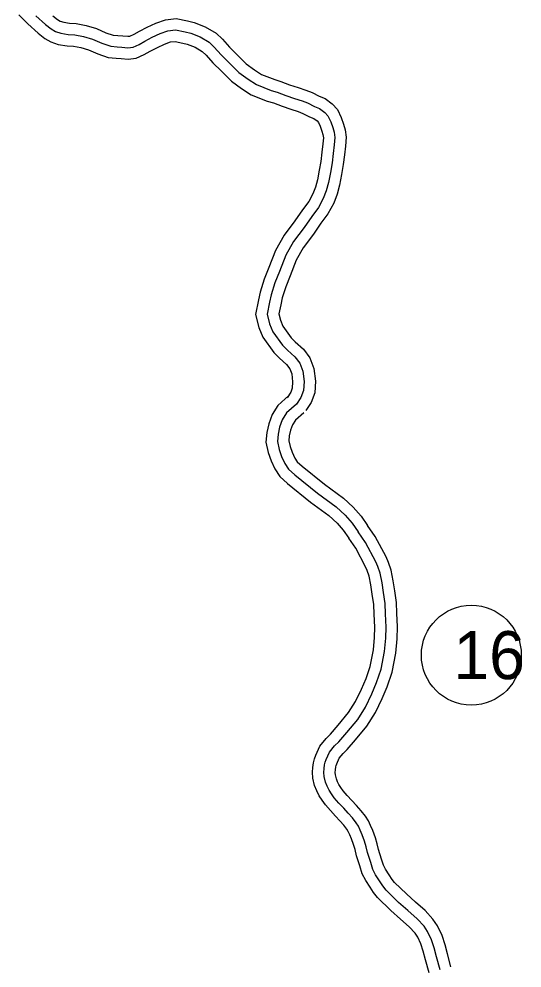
# Model space of a CAD drawing. Extents: x 31699 to 244310, y -8841 to 11474.
# Drawn here: x 96930 to 97373, y 7933 to 8769 of the extents above; entities that cross this region are included whole.
import ezdxf

# ---------------------------------------------------------------- set-up
doc = ezdxf.new("R2010")
doc.units = 0
for name, color, linetype in [('B_Logo', 7, 'Continuous'), ('R_Border Notes', 7, 'Continuous'), ('R_XS_EARTHWORK_STAGE2', 7, 'Continuous')]:
    doc.layers.add(name, color=color, linetype=linetype)

msp = doc.modelspace()

# ---------------------------------------------------------------- linework, layer by layer
at = {"layer": 'B_Logo'}
for points in [[(96945, 8771.56), (96953.67, 8763.78), (96958.51, 8759.97), (96962.46, 8757.74), (96967.2, 8756.06), (96973.67, 8754.93), (96979.47, 8754.67), (96987.13, 8753.35), (96995.15, 8750.84), (97003.31, 8747.26), (97011.06, 8744.68), (97016.66, 8744.08), (97020.99, 8743.86), (97026.19, 8743.39), (97030.77, 8743.97), (97036.14, 8746.37), (97041.16, 8749.1), (97047.71, 8752.64), (97054.53, 8755.86), (97061.43, 8758.27), (97068.14, 8759.02), (97076.68, 8757.31), (97081.55, 8756.17), (97089.71, 8752.86), (97097.75, 8748.14), (97102.26, 8743.86), (97108.33, 8736.99), (97115.6, 8729.8), (97123.94, 8721.68), (97132, 8715.7), (97139.37, 8710.92), (97152.21, 8705.86), (97157.55, 8704.18), (97165.31, 8701.27), (97172.92, 8698.82), (97179.6, 8696.56), (97184.42, 8694.75), (97190.44, 8691.68), (97194.79, 8689.79), (97199.49, 8686.38), (97202.32, 8683.27), (97204.84, 8678.23), (97206.56, 8673.05), (97207.8, 8668.99), (97208.32, 8664.26), (97207.93, 8657.78), (97206.95, 8650.16), (97205.98, 8641.88), (97204.54, 8633.65), (97202.84, 8624.69), (97200.79, 8617.39), (97198.27, 8610.62), (97193.9, 8602.63), (97188.07, 8594.76), (97181.39, 8584.94), (97172.07, 8572.82), (97165.29, 8560.67), (97159.66, 8546.19), (97155.71, 8536.27), (97152.43, 8525.69), (97150.97, 8519.26), (97148.7, 8508.69), (97150.99, 8500.25), (97153.86, 8493.27), (97162.31, 8481.49), (97166.69, 8477.2), (97173.28, 8471.21), (97177.54, 8465.51), (97180.21, 8458.61), (97181.31, 8449.48), (97180.8, 8441.66), (97178.6, 8435.5), (97174.61, 8429.51)], [(97174.61, 8429.51), (97165.98, 8421.87), (97162.12, 8415.82), (97159.79, 8409.39), (97158.4, 8403.04), (97157.87, 8396.69), (97159.28, 8389.57), (97161.48, 8383.52), (97164.35, 8377.28), (97167.53, 8372.24), (97173.25, 8367.24), (97193.13, 8351.25), (97209.64, 8339.16), (97217.51, 8331.78), (97223.71, 8324.84), (97229.05, 8317.03)], [(97301.02, 7931.31), (97297.87, 7942.88), (97295.84, 7950.73), (97293.55, 7957.91), (97290.13, 7965.21), (97286.94, 7969.84), (97280.93, 7976.36), (97272.79, 7983.6), (97264.57, 7990.83), (97253.52, 8001.63), (97250.68, 8005.27), (97247.82, 8009.7), (97244.22, 8015.13), (97241.9, 8019.77), (97240.03, 8025.88), (97237.12, 8034.59), (97235.85, 8039.71), (97234.52, 8044.7), (97232.45, 8050.35), (97230.74, 8054.33), (97229.1, 8057.85), (97227.19, 8060.96), (97223.94, 8065.12), (97220.23, 8069.34), (97216.18, 8073.63), (97211.93, 8078.24), (97207.87, 8082.93), (97205.37, 8086.37), (97203.33, 8089.54), (97201.62, 8092.99), (97200.17, 8096.71), (97198.98, 8101.64), (97198.73, 8105.3), (97199.09, 8108.58), (97199.44, 8111.92), (97200.01, 8114.26), (97200.85, 8116.61), (97203.76, 8122.99), (97208.21, 8128.52), (97211.82, 8132.18), (97218.84, 8140.35), (97228.6, 8151.96), (97235.45, 8162.73), (97240.89, 8174.35), (97245.22, 8184.28), (97249.26, 8196.02), (97252.25, 8211.68), (97253.3, 8223.44), (97253.5, 8233.25), (97253.08, 8244.93), (97252.63, 8254), (97251.24, 8263.6), (97250, 8272.19), (97248.23, 8280.71), (97246.35, 8286.63), (97244.5, 8290.81), (97235.36, 8307.84), (97229.05, 8317.03)]]:
    msp.add_lwpolyline(points, dxfattribs=at)
at = {"layer": 'R_Border Notes'}
msp.add_circle((97328.61, 8208.51), 44, dxfattribs=at)
at = {"layer": 'R_XS_EARTHWORK_STAGE2'}
for points in [[(96930.3, 8772.49), (96938.03, 8764.37), (96947.23, 8756.12), (96952.92, 8751.63), (96958.31, 8748.6), (96964.66, 8746.35), (96972.58, 8744.97), (96978.39, 8744.71), (96984.79, 8743.61), (96991.64, 8741.46), (96999.72, 8737.92), (97008.92, 8734.86), (97015.87, 8734.11), (97020.28, 8733.89), (97026.37, 8733.33), (97033.5, 8734.24), (97040.57, 8737.4), (97045.93, 8740.31), (97052.23, 8743.72), (97058.33, 8746.59), (97063.66, 8748.46), (97067.71, 8748.91), (97074.56, 8747.54), (97078.51, 8746.61), (97085.28, 8743.86), (97091.7, 8740.1), (97095.05, 8736.91), (97101.06, 8730.11), (97108.6, 8722.66), (97117.45, 8714.05), (97126.29, 8707.49), (97134.77, 8701.98), (97148.88, 8696.42), (97154.3, 8694.72), (97162.01, 8691.82), (97169.79, 8689.32), (97176.24, 8687.14), (97180.37, 8685.58), (97186.18, 8682.63), (97189.8, 8681.06), (97192.78, 8678.89), (97193.99, 8677.56), (97195.57, 8674.4), (97197.03, 8670), (97197.96, 8666.96), (97198.29, 8664.01), (97197.97, 8658.72), (97197.02, 8651.38), (97196.08, 8643.32), (97194.7, 8635.44), (97193.1, 8626.98), (97191.28, 8620.49), (97189.15, 8614.79), (97185.46, 8608.04), (97179.91, 8600.55), (97173.28, 8590.81), (97163.7, 8578.34), (97156.22, 8564.94), (97150.35, 8549.85), (97146.27, 8539.6), (97142.77, 8528.28), (97141.21, 8521.42), (97138.41, 8508.42), (97141.5, 8497.02), (97145.06, 8488.39), (97154.69, 8474.96), (97159.82, 8469.93), (97165.84, 8464.45), (97168.7, 8460.62), (97170.43, 8456.16), (97171.27, 8449.2), (97170.91, 8443.7), (97169.6, 8440.02), (97166.29, 8435.06)], [(96960.11, 8771.44), (96964.09, 8768.3), (96966.61, 8766.88), (96969.75, 8765.77), (96974.76, 8764.89), (96980.54, 8764.63), (96989.48, 8763.1), (96998.66, 8760.22), (97006.91, 8756.61), (97013.2, 8754.51), (97017.45, 8754.05), (97021.69, 8753.84), (97026, 8753.45), (97028.04, 8753.71), (97031.71, 8755.35), (97036.4, 8757.89), (97043.2, 8761.57), (97050.74, 8765.12), (97059.2, 8768.09), (97068.58, 8769.13), (97078.81, 8767.09), (97084.6, 8765.72), (97094.14, 8761.85), (97103.81, 8756.19), (97109.47, 8750.8), (97115.6, 8743.86), (97122.6, 8736.94), (97130.44, 8729.32), (97137.7, 8723.92), (97143.97, 8719.85), (97155.54, 8715.29), (97160.81, 8713.64), (97168.6, 8710.71), (97176.05, 8708.32), (97182.97, 8705.98), (97188.46, 8703.91), (97194.7, 8700.73), (97199.78, 8698.53), (97206.19, 8693.87), (97210.64, 8688.99), (97214.1, 8682.06), (97216.09, 8676.09), (97217.64, 8671.02), (97218.35, 8664.5), (97217.89, 8656.84), (97216.87, 8648.94), (97215.88, 8640.43), (97214.38, 8631.86), (97212.59, 8622.4), (97210.31, 8614.29), (97207.39, 8606.46), (97202.35, 8597.23), (97196.22, 8588.97), (97189.49, 8579.08), (97180.45, 8567.31), (97174.35, 8556.4), (97168.96, 8542.53), (97165.14, 8532.93), (97162.1, 8523.1), (97160.74, 8517.1), (97158.98, 8508.96), (97160.47, 8503.47), (97162.66, 8498.16), (97169.93, 8488.02), (97173.55, 8484.47), (97180.71, 8477.96), (97186.37, 8470.41), (97189.99, 8461.05), (97191.35, 8449.75), (97190.69, 8439.62), (97187.61, 8430.98), (97182.93, 8423.96)], [(97167.98, 8437), (97158.3, 8428.43), (97153.09, 8420.27), (97150.17, 8412.17), (97148.49, 8404.53), (97147.79, 8396.12), (97149.62, 8386.87), (97152.22, 8379.72), (97155.54, 8372.5), (97159.85, 8365.68), (97166.81, 8359.58), (97187.04, 8343.32), (97203.24, 8331.45), (97210.35, 8324.78), (97215.82, 8318.66), (97220.8, 8311.38)], [(97181.24, 8422.02), (97173.65, 8415.31), (97171.15, 8411.38), (97169.42, 8406.61), (97168.31, 8401.54), (97167.95, 8397.26), (97168.94, 8392.26), (97170.74, 8387.32), (97173.16, 8382.06), (97175.21, 8378.81), (97179.68, 8374.9), (97199.22, 8359.18), (97216.04, 8346.87), (97224.67, 8338.77), (97231.6, 8331.02), (97237.3, 8322.68)], [(97310.67, 7933.93), (97307.54, 7945.44), (97305.45, 7953.5), (97302.88, 7961.57), (97298.83, 7970.2), (97294.78, 7976.09), (97287.95, 7983.51), (97279.41, 7991.09), (97271.38, 7998.17), (97260.98, 8008.32), (97258.84, 8011.06), (97256.2, 8015.17), (97252.9, 8020.15), (97251.22, 8023.5), (97249.55, 8028.94), (97246.73, 8037.38), (97245.54, 8042.2), (97244.07, 8047.72), (97241.75, 8054.05), (97239.86, 8058.43), (97237.92, 8062.59), (97235.42, 8066.66), (97231.64, 8071.5), (97227.62, 8076.08), (97223.49, 8080.45), (97219.39, 8084.9), (97215.71, 8089.16), (97213.62, 8092.02), (97212.04, 8094.48), (97210.78, 8097.03), (97209.73, 8099.72), (97208.9, 8103.16), (97208.77, 8105.1), (97209.03, 8107.51), (97209.32, 8110.21), (97209.61, 8111.4), (97210.12, 8112.85), (97212.33, 8117.7), (97215.68, 8121.86), (97219.18, 8125.39), (97226.46, 8133.87), (97236.69, 8146.03), (97244.24, 8157.91), (97250, 8170.23), (97254.55, 8180.65), (97258.95, 8193.44), (97262.17, 8210.29), (97263.29, 8222.89), (97263.51, 8233.33), (97263.07, 8245.36), (97262.6, 8254.97), (97261.14, 8265.03), (97259.85, 8273.93), (97257.91, 8283.25), (97255.72, 8290.17), (97253.49, 8295.2), (97243.92, 8313.05), (97237.3, 8322.69)], [(97291.37, 7928.69), (97288.21, 7940.32), (97286.23, 7947.96), (97284.22, 7954.25), (97281.42, 7960.21), (97279.1, 7963.58), (97273.91, 7969.22), (97266.16, 7976.11), (97257.77, 7983.5), (97246.05, 7994.95), (97242.51, 7999.47), (97239.45, 8004.23), (97235.55, 8010.11), (97232.59, 8016.04), (97230.5, 8022.83), (97227.5, 8031.8), (97226.17, 8037.23), (97224.98, 8041.69), (97223.16, 8046.65), (97221.61, 8050.23), (97220.27, 8053.11), (97218.96, 8055.25), (97216.24, 8058.74), (97212.84, 8062.6), (97208.87, 8066.81), (97204.47, 8071.58), (97200.04, 8076.7), (97197.11, 8080.72), (97194.61, 8084.61), (97192.46, 8088.95), (97190.61, 8093.71), (97189.06, 8100.11), (97188.69, 8105.51), (97189.14, 8109.65), (97189.57, 8113.64), (97190.42, 8117.13), (97191.57, 8120.37), (97195.18, 8128.28), (97200.74, 8135.19), (97204.47, 8138.96), (97211.22, 8146.82), (97220.52, 8157.88), (97226.67, 8167.55), (97231.78, 8178.46), (97235.89, 8187.91), (97239.57, 8198.6), (97242.34, 8213.06), (97243.31, 8223.99), (97243.5, 8233.18), (97243.09, 8244.5), (97242.67, 8253.03), (97241.35, 8262.16), (97240.15, 8270.45), (97238.54, 8278.17), (97236.99, 8283.08), (97235.51, 8286.41), (97226.81, 8302.63), (97220.81, 8311.38)]]:
    msp.add_lwpolyline(points, dxfattribs=at)

# ---------------------------------------------------------------- texts
at = {"layer": 'R_Border Notes'}
msp.add_text('16', height=42.24, dxfattribs=at).set_placement((97312.87, 8187.39))

doc.saveas('drawing.dxf')
